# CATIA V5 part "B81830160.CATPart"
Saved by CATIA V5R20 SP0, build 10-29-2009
Part number: B81830160
Revision: 4
Definition: design
Nomenclature: B81830160
Source: made
Description: NOT SPECIFIED
Bounding box of the stored display mesh (mm): x -17.817 to 17.817, y -18 to 18, z 0 to 160
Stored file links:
  C:\Users\Raffaele\Desktop\3D X SITO CF\BOLEX\6-PILLAR REF 818\B81830160.CATPart
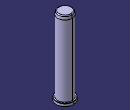
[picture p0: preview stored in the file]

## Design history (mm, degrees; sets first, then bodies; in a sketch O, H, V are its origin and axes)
Body1 "MANIFOLD_SOLID_BREP #370" (main body)
  Solid1: solid without history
